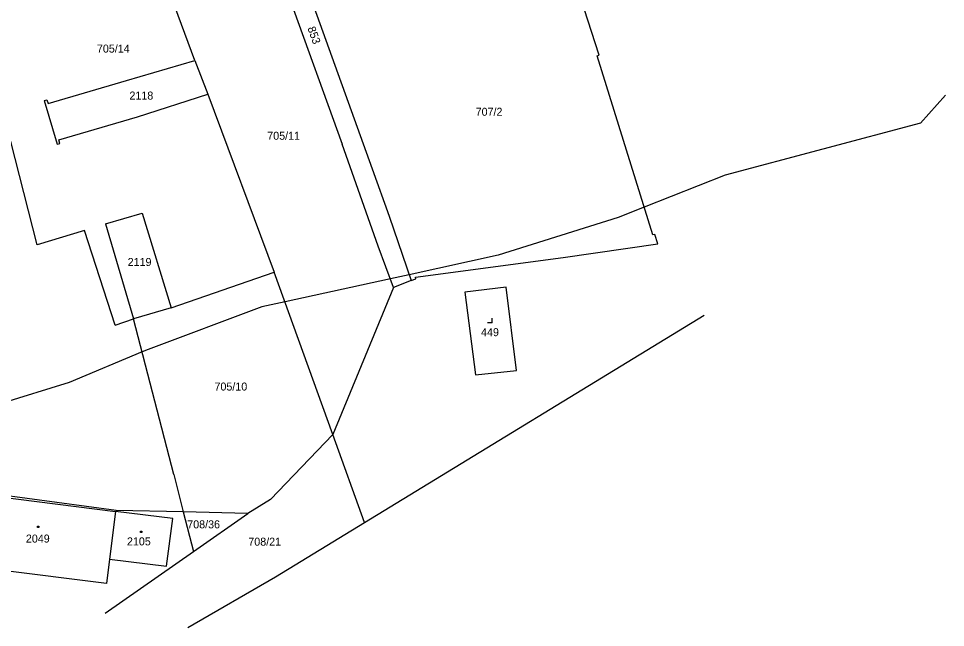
# Model space of a CAD drawing. Extents: x -711879 to -711361, y -1048782 to -1048177.
# Drawn here: x -711557.6 to -711360.9, y -1048729 to -1048599.8 of the extents above; entities that cross this region are included whole.
import ezdxf

# ---------------------------------------------------------------- set-up
doc = ezdxf.new("R2010")
doc.units = 0
for name, color, linetype in [('Vrstva 1', 7, 'Continuous'), ('Vrstva 14', 7, 'Continuous'), ('Vrstva 15', 7, 'Continuous'), ('Vrstva 21', 7, 'Continuous'), ('Vrstva 23', 7, 'Continuous'), ('Vrstva 25', 7, 'Continuous'), ('Vrstva 46', 7, 'Continuous')]:
    doc.layers.add(name, color=color, linetype=linetype)

msp = doc.modelspace()

# ---------------------------------------------------------------- linework, layer by layer
at = {"layer": 'Vrstva 1'}
for p, q in [((-711505.42, -1048580.81), (-711488.95, -1048626.45)), ((-711434.36, -1048607.51), (-711442.86, -1048581.35)), ((-711553.71, -1048647.83), (-711570.11, -1048583.49)), ((-711520.21, -1048608.66), (-711527.11, -1048589.92)), ((-711495.62, -1048595.46), (-711482.57, -1048631.65)), ((-711534.73, -1048612.9), (-711520.21, -1048608.66)), ((-711520.21, -1048608.66), (-711517.47, -1048615.85)), ((-711434.81, -1048607.67), (-711434.36, -1048607.51)), ((-711423.01, -1048645.7), (-711434.81, -1048607.67)), ((-711551.37, -1048617.79), (-711534.73, -1048612.9)), ((-711532.37, -1048620.6), (-711517.47, -1048615.85)), ((-711517.47, -1048615.85), (-711503.34, -1048653.61)), ((-711552.19, -1048617.18), (-711551.61, -1048617.03)), ((-711552.19, -1048617.18), (-711549.44, -1048626.45)), ((-711551.61, -1048617.03), (-711551.37, -1048617.79)), ((-711549.1, -1048625.52), (-711532.37, -1048620.6)), ((-711549.44, -1048626.45), (-711548.86, -1048626.29)), ((-711548.86, -1048626.29), (-711549.1, -1048625.52)), ((-711481.28, -1048648.09), (-711488.95, -1048626.45)), ((-711482.57, -1048631.65), (-711478.96, -1048641.73)), ((-711539.16, -1048643.38), (-711531.39, -1048641.06)), ((-711531.39, -1048641.06), (-711525.21, -1048661.17)), ((-711478.96, -1048641.73), (-711474.27, -1048655.4)), ((-711539.16, -1048643.38), (-711533.2, -1048663.52)), ((-711543.64, -1048644.75), (-711553.71, -1048647.83)), ((-711537.16, -1048664.83), (-711543.64, -1048644.75)), ((-711422.53, -1048645.59), (-711423.01, -1048645.7)), ((-711421.9, -1048647.62), (-711422.53, -1048645.59)), ((-711478.02, -1048656.85), (-711481.28, -1048648.09)), ((-711442.01, -1048650.53), (-711421.9, -1048647.62)), ((-711473.39, -1048654.7), (-711442.01, -1048650.53)), ((-711525.21, -1048661.17), (-711503.34, -1048653.61)), ((-711490.89, -1048688.05), (-711503.34, -1048653.61)), ((-711474.27, -1048655.4), (-711478.02, -1048656.85)), ((-711474.27, -1048655.4), (-711473.28, -1048655)), ((-711473.28, -1048655), (-711473.39, -1048654.7)), ((-711478.02, -1048656.85), (-711490.89, -1048688.05)), ((-711454.14, -1048656.8), (-711462.89, -1048657.88)), ((-711462.89, -1048657.88), (-711460.61, -1048675.42)), ((-711451.94, -1048674.46), (-711454.14, -1048656.8)), ((-711525.21, -1048661.17), (-711533.2, -1048663.52)), ((-711537.16, -1048664.83), (-711533.2, -1048663.52)), ((-711524.67, -1048696.57), (-711533.2, -1048663.52)), ((-711484.2, -1048706.72), (-711412.11, -1048662.75)), ((-711460.61, -1048675.42), (-711451.94, -1048674.46)), ((-711490.89, -1048688.05), (-711504.18, -1048701.87)), ((-711484.2, -1048706.72), (-711490.89, -1048688.05)), ((-711524.67, -1048696.57), (-711522.68, -1048704.51)), ((-711568.68, -1048700.42), (-711537.05, -1048704.38)), ((-711536.89, -1048704.2), (-711564.15, -1048700.53)), ((-711504.18, -1048701.87), (-711508.95, -1048704.81)), ((-711537.05, -1048704.38), (-711538.33, -1048714.52)), ((-711522.68, -1048704.51), (-711536.89, -1048704.2)), ((-711522.68, -1048704.51), (-711520.52, -1048712.92)), ((-711508.95, -1048704.81), (-711522.68, -1048704.51)), ((-711520.52, -1048712.92), (-711508.95, -1048704.81)), ((-711503.12, -1048718.25), (-711484.2, -1048706.72)), ((-711539.23, -1048726.03), (-711520.52, -1048712.92)), ((-711538.33, -1048714.52), (-711538.98, -1048719.68)), ((-711538.98, -1048719.68), (-711570.6, -1048715.76)), ((-711521.72, -1048729.03), (-711503.12, -1048718.25))]:
    msp.add_line(p, q, dxfattribs=at)
msp.add_lwpolyline([(-711538.33, -1048714.52), (-711526.21, -1048716.05), (-711524.91, -1048705.91), (-711537.05, -1048704.38)], dxfattribs=at)
at = {"layer": 'Vrstva 21'}
msp.add_lwpolyline([(-711360.87, -1048616), (-711366.19, -1048622), (-711407.63, -1048633), (-711424.84, -1048639.81), (-711430.37, -1048642), (-711455.81, -1048650), (-711474.7, -1048654.14), (-711478.7, -1048655.02), (-711501.06, -1048659.92), (-711506, -1048661), (-711530.13, -1048670), (-711531.39, -1048670.53), (-711546.88, -1048677), (-711561.57, -1048681.58)], dxfattribs=at)
at = {"layer": 'Vrstva 23'}
for q in [(-711457.09, -1048663.36), (-711458.09, -1048664.36)]:
    msp.add_line((-711457.09, -1048664.36), q, dxfattribs=at)
at = {"layer": 'Vrstva 25'}
for p, q in [((-711553.6, -1048707.53), (-711553.3, -1048707.53)), ((-711553.6, -1048707.83), (-711553.6, -1048707.53)), ((-711553.3, -1048707.83), (-711553.6, -1048707.83)), ((-711553.3, -1048707.53), (-711553.3, -1048707.83)), ((-711531.76, -1048708.57), (-711531.46, -1048708.57)), ((-711531.76, -1048708.87), (-711531.76, -1048708.57)), ((-711531.46, -1048708.87), (-711531.76, -1048708.87)), ((-711531.46, -1048708.57), (-711531.46, -1048708.87))]:
    msp.add_line(p, q, dxfattribs=at)
at = {"layer": 'Vrstva 46'}
for p, q in [((-711534.73, -1048612.9), (-711534.73, -1048612.9)), ((-711532.37, -1048620.6), (-711532.37, -1048620.6)), ((-711531.39, -1048641.06), (-711531.39, -1048641.06)), ((-711553.71, -1048647.83), (-711553.71, -1048647.83)), ((-711478.02, -1048656.85), (-711478.02, -1048656.85)), ((-711525.21, -1048661.17), (-711525.21, -1048661.17)), ((-711497.15, -1048670.72), (-711497.15, -1048670.72)), ((-711451.94, -1048674.46), (-711451.94, -1048674.46)), ((-711494.77, -1048677.31), (-711494.77, -1048677.31)), ((-711490.89, -1048688.05), (-711490.89, -1048688.05)), ((-711504.18, -1048701.87), (-711504.18, -1048701.87)), ((-711536.89, -1048704.2), (-711536.89, -1048704.2)), ((-711508.95, -1048704.81), (-711508.95, -1048704.81)), ((-711520.52, -1048712.92), (-711520.52, -1048712.92))]:
    msp.add_line(p, q, dxfattribs=at)

# ---------------------------------------------------------------- texts
at = {"layer": 'Vrstva 14'}
msp.add_text('853', height=1.7, rotation=289.72413, dxfattribs=at).set_placement((-711496.33, -1048601.8))
for s, p in [('705/14', (-711541, -1048607)), ('2118', (-711534.093, -1048616.97)), ('707/2', (-711460.6, -1048620.41)), ('705/11', (-711504.84, -1048625.5)), ('2119', (-711534.473, -1048652.3)), ('705/10', (-711516.04, -1048678.74)), ('708/36', (-711521.825, -1048707.99)), ('708/21', (-711508.86, -1048711.67))]:
    msp.add_text(s, height=1.7, dxfattribs=at).set_placement(p)
at = {"layer": 'Vrstva 15'}
for s, p in [('449', (-711459.45, -1048667.2)), ('2049', (-711556.08, -1048711.01)), ('2105', (-711534.625, -1048711.61))]:
    msp.add_text(s, height=1.7, dxfattribs=at).set_placement(p)

doc.saveas('drawing.dxf')
